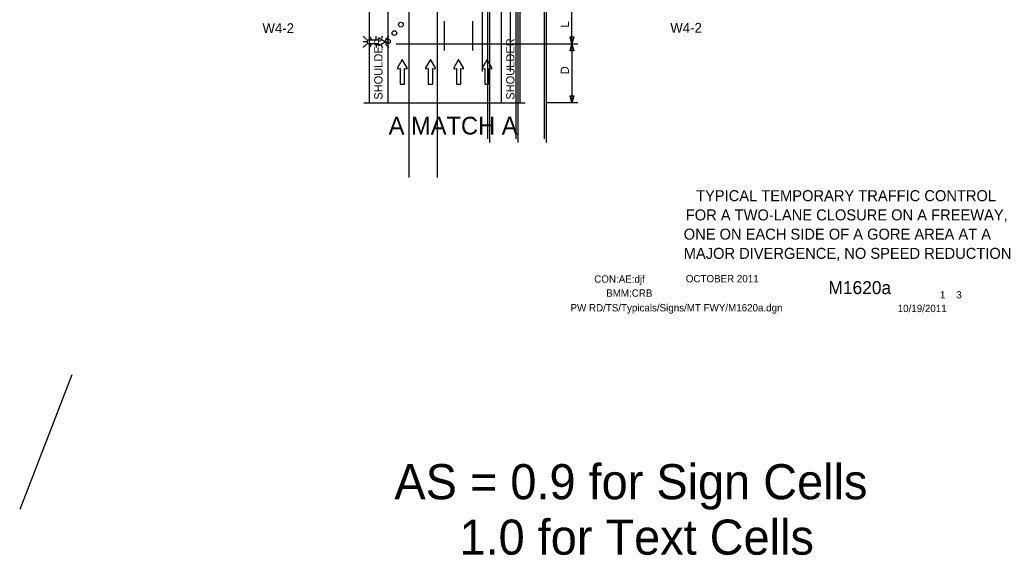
# Model space of a CAD drawing. Extents: x 16604 to 19504, y 6997 to 8305.
# Drawn here: x 16604 to 17443, y 7013 to 7467 of the extents above; entities that cross this region are included whole.
import ezdxf

# ---------------------------------------------------------------- set-up
doc = ezdxf.new("R2010")
doc.units = 0
for name, color, linetype in [('ALI_LEGAL_EX', 7, 'Continuous'), ('BORDER', 7, 'Continuous'), ('BORDER_SIGNAL_WO', 7, 'Continuous'), ('MT_SCRATCH_LEVEL_E', 7, 'Continuous'), ('PAVT_EDGE_EX', 7, 'Continuous'), ('TRAFFIC_SIGNS_PR', 7, 'Continuous'), ('TYPICAL_TEXT_DIMEN_PR', 7, 'Continuous')]:
    doc.layers.add(name, color=color, linetype=linetype)

msp = doc.modelspace()

# ---------------------------------------------------------------- linework, layer by layer
at = {"layer": 'ALI_LEGAL_EX'}
for p, q in [((16995.53, 8241.3), (16995.53, 7423.16)), ((17019.53, 8241.3), (17019.53, 7423.16)), ((17000.51, 7366.28), (17000.51, 7976.48)), ((17024.51, 7366.28), (17024.51, 7976.48)), ((17048.51, 7366.28), (17048.51, 7976.48)), ((17002.26, 7363.06), (17002.26, 7973.25)), ((17026.26, 7363.06), (17026.26, 7973.25)), ((17050.26, 7363.06), (17050.26, 7973.25)), ((16933.79, 7333.59), (16933.79, 7943.78)), ((16933.79, 7333.59), (16933.79, 7943.78)), ((16957.79, 7333.59), (16957.79, 7943.78))]:
    msp.add_line(p, q, dxfattribs=at)
for points in [[(16963.73, 7441.09), (16963.73, 7466.09)], [(16987.73, 7441.09), (16987.73, 7466.09)]]:
    msp.add_lwpolyline(points, dxfattribs=at)
at = {"layer": 'MT_SCRATCH_LEVEL_E'}
for p, q in [((16927.92, 7433.52), (16923.81, 7426.28)), ((16932.07, 7426.28), (16927.92, 7433.52)), ((16951.83, 7433.52), (16947.71, 7426.28)), ((16955.97, 7426.28), (16951.83, 7433.52)), ((16975.73, 7433.52), (16971.62, 7426.28)), ((16979.88, 7426.28), (16975.73, 7433.52)), ((16999.78, 7433.52), (16995.67, 7426.28)), ((17003.93, 7426.28), (16999.78, 7433.52)), ((16924.29, 7425.6), (16926.07, 7425.91)), ((16926.07, 7425.91), (16926.07, 7412.65)), ((16929.81, 7412.65), (16929.81, 7425.91)), ((16929.81, 7425.91), (16931.59, 7425.6)), ((16948.2, 7425.6), (16949.97, 7425.91)), ((16949.97, 7425.91), (16949.97, 7412.65)), ((16953.72, 7412.65), (16953.72, 7425.91)), ((16953.72, 7425.91), (16955.49, 7425.6)), ((16972.1, 7425.6), (16973.88, 7425.91)), ((16973.88, 7425.91), (16973.88, 7412.65)), ((16977.62, 7412.65), (16977.62, 7425.91)), ((16977.62, 7425.91), (16979.4, 7425.6)), ((16996.15, 7425.6), (16997.93, 7425.91)), ((16997.93, 7425.91), (16997.93, 7412.65)), ((17001.67, 7412.65), (17001.67, 7425.91)), ((17001.67, 7425.91), (17003.45, 7425.6)), ((16926.07, 7412.65), (16929.81, 7412.65)), ((16949.97, 7412.65), (16953.72, 7412.65)), ((16973.88, 7412.65), (16977.62, 7412.65)), ((16997.93, 7412.65), (17001.67, 7412.65))]:
    msp.add_line(p, q, dxfattribs=at)
for centre, start, end in [((16924.22, 7426.05), 150.42484, 279.96381), ((16931.66, 7426.06), 260.03619, 29.77312), ((16948.12, 7426.05), 150.42484, 279.96381), ((16955.56, 7426.06), 260.03619, 29.77312), ((16972.03, 7426.05), 150.42484, 279.96381), ((16979.47, 7426.06), 260.03619, 29.77312), ((16996.08, 7426.05), 150.42484, 279.96381), ((17003.52, 7426.06), 260.03619, 29.77312)]:
    msp.add_arc(centre, 0.463, start, end, dxfattribs=at)
at = {"layer": 'PAVT_EDGE_EX'}
for p, q in [((16899.73, 7751.28), (16899.73, 7396.71)), ((16915.73, 7751.28), (16915.73, 7396.71)), ((17011.73, 7751.28), (17011.73, 7396.71)), ((17027.73, 7751.28), (17027.73, 7396.71))]:
    msp.add_line(p, q, dxfattribs=at)
at = {"layer": 'TRAFFIC_SIGNS_PR'}
for p, q in [((16897.63, 7450.42), (16894.81, 7453.24)), ((16897.63, 7448.39), (16894.81, 7448.39)), ((16899.93, 7453.24), (16901.56, 7450.42)), ((16905.72, 7450.42), (16905.72, 7453.24)), ((16911.19, 7453.24), (16909.98, 7451.15)), ((16916.62, 7453.24), (16913.8, 7450.42)), ((16913.8, 7448.39), (16916.62, 7448.39)), ((16897.63, 7446.36), (16894.81, 7443.54)), ((16901.58, 7446.36), (16899.95, 7443.54)), ((16905.72, 7446.36), (16905.72, 7443.54)), ((16909.9, 7445.72), (16911.16, 7443.54)), ((16916.62, 7443.54), (16913.8, 7446.36))]:
    msp.add_line(p, q, dxfattribs=at)
for points in [[(16907.54, 7451.07), (16907.77, 7449.78), (16898.05, 7449.78), (16898.05, 7447.03), (16907.77, 7447.03), (16907.54, 7445.73)], [(16908.04, 7445.38), (16913.35, 7448.39), (16908.04, 7451.43)]]:
    msp.add_lwpolyline(points, dxfattribs=at)
for centre in [(16926.73, 7463.01), (16921.24, 7455.88), (16915.74, 7448.75)]:
    msp.add_circle(centre, 2, dxfattribs=at)
for centre, start, end in [((16907.88, 7451.13), 61.48329, 189.95933), ((16907.88, 7445.67), 170.73078, 298.89165)]:
    msp.add_arc(centre, 0.341, start, end, dxfattribs=at)
at = {"layer": 'TYPICAL_TEXT_DIMEN_PR'}
for p, q in [((17071.73, 7446.71), (17071.73, 7477.27)), ((17071.73, 7446.71), (17070.16, 7452.57)), ((17070.16, 7452.57), (17071.73, 7452.57)), ((17071.73, 7452.57), (17073.3, 7452.57)), ((17073.3, 7452.57), (17071.73, 7446.71)), ((16922.69, 7446.71), (17076.73, 7446.71)), ((17070.16, 7440.85), (17071.73, 7446.71)), ((17071.73, 7440.85), (17070.16, 7440.85)), ((17071.73, 7446.71), (17071.73, 7396.71)), ((17071.73, 7446.71), (17073.3, 7440.85)), ((17073.3, 7440.85), (17071.73, 7440.85)), ((16895.43, 7396.71), (17032.08, 7396.71)), ((17076.73, 7396.71), (17050.73, 7396.71)), ((17071.73, 7396.71), (17070.16, 7402.57)), ((17070.16, 7402.57), (17071.73, 7402.57)), ((17071.73, 7402.57), (17073.3, 7402.57)), ((17073.3, 7402.57), (17071.73, 7396.71)), ((16647.75, 7166.25), (16603.71, 7052.16))]:
    msp.add_line(p, q, dxfattribs=at)

# ---------------------------------------------------------------- texts
at = {"layer": 'BORDER'}
for s, p in [('TYPICAL TEMPORARY TRAFFIC CONTROL', (17177.02, 7313.39)), ('FOR A TWO-LANE CLOSURE ON A FREEWAY,', (17168.26, 7297.1)), ('ONE ON EACH SIDE OF A GORE AREA AT A', (17166.5, 7280.81)), ('MAJOR DIVERGENCE, NO SPEED REDUCTION', (17166.52, 7264.52))]:
    msp.add_text(s, height=9.3, dxfattribs=at).set_placement(p)
at = {"layer": 'BORDER_SIGNAL_WO'}
for s, height, p in [('CON:AE:djf  ', 6.2, (17090.69, 7244.31)), ('    OCTOBER 2011    ', 6.2, (17159.08, 7244.59)), ('    M1620a   ', 11, (17272.86, 7234.63)), ('BMM:CRB   ', 6.2, (17100.81, 7232.42)), (' 1    3 ', 6.2, (17381.45, 7230.95)), ('PW RD/TS/Typicals/Signs/MT FWY/M1620a.dgn      ', 6.2, (17070.55, 7219.96)), ('10/19/2011    ', 6.2, (17347.93, 7219.38)), ('AS = 0.9 for Sign Cells', 29.7271, (16921.23, 7060.76)), ('     1.0 for Text Cells', 29.7271, (16921.23, 7013.76))]:
    msp.add_text(s, height=height, dxfattribs=at).set_placement(p)
at = {"layer": 'TRAFFIC_SIGNS_PR'}
for p in [(16809.42, 7455.83), (17155.16, 7456.15)]:
    msp.add_text('W4-2', height=8.37, dxfattribs=at).set_placement(p)
at = {"layer": 'TYPICAL_TEXT_DIMEN_PR'}
for s, p in [('L', (17069.17, 7460.56)), ('SHOULDER', (16911.17, 7399.41)), ('SHOULDER', (17023.03, 7399.41)), ('D', (17069.17, 7420.93))]:
    msp.add_text(s, height=7, rotation=90, dxfattribs=at).set_placement(p)
msp.add_text('A MATCH A', height=15, dxfattribs=at).set_placement((16916.4, 7369.9))

doc.saveas('drawing.dxf')
